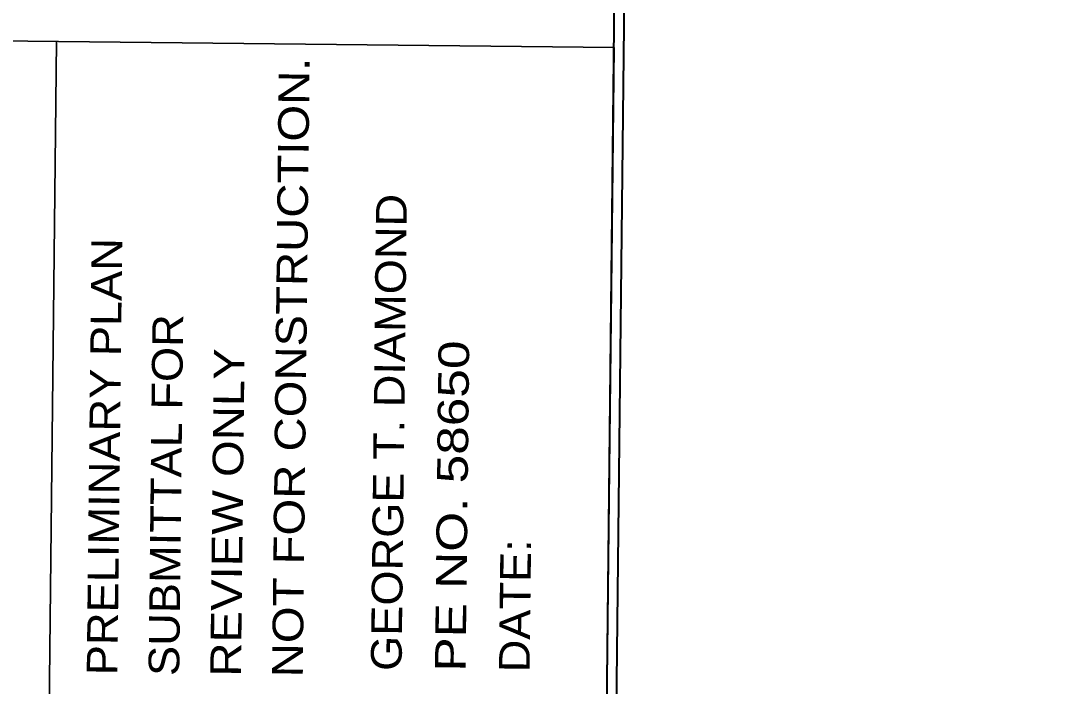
# Model space of a CAD drawing. Extents: x 2356576 to 2377878, y 6966390 to 6990634.
# Drawn here: x 2366630 to 2367164, y 6969128 to 6969467 of the extents above; entities that cross this region are included whole.
import ezdxf

# ---------------------------------------------------------------- set-up
doc = ezdxf.new("R2010")
doc.units = 0
doc.header["$LTSCALE"] = 7.1
doc.layers.add('19', color=7, linetype='Continuous', lineweight=13)
doc.layers.add('8', color=7, linetype='Continuous', lineweight=13)

msp = doc.modelspace()

# ---------------------------------------------------------------- linework, layer by layer
at = {"layer": '19', "lineweight": 35}
for p, q in [((2366931.855, 6969453.45), (2366226.339, 6969461.286)), ((2366647.707, 6969456.606), (2366638.741, 6968649.392)), ((2366931.855, 6969453.45), (2366922.891, 6968646.236))]:
    msp.add_line(p, q, dxfattribs=at)
at = {"layer": '19', "lineweight": 40}
msp.add_lwpolyline([(2363758.773, 6990629.355), (2367158.576, 6990592.767), (2366922.891, 6968646.236), (2363523.088, 6968682.826)], close=True, dxfattribs=at)
at = {"layer": '8', "lineweight": 35}
for p, q in [((2366931.855, 6969453.45), (2366226.339, 6969461.286)), ((2366647.707, 6969456.606), (2366638.741, 6968649.392)), ((2366931.855, 6969453.45), (2366922.891, 6968646.236))]:
    msp.add_line(p, q, dxfattribs=at)
at = {"layer": '8', "lineweight": 40}
for points in [[(2363753.827, 6990634.409), (2367163.63, 6990597.713), (2366927.837, 6968641.182), (2363518.034, 6968677.88)], [(2363758.773, 6990629.355), (2367158.576, 6990592.767), (2366922.891, 6968646.236), (2363523.088, 6968682.826)]]:
    msp.add_lwpolyline(points, close=True, dxfattribs=at)

# ---------------------------------------------------------------- texts
at = {"layer": '19'}
for s, height, width, p in [('NOT FOR CONSTRUCTION.', 15.66, 1.15, (2366773.139, 6969132.546)), ('GEORGE T. DIAMOND', 15.65, 1.1, (2366823.485, 6969135.828)), ('PRELIMINARY PLAN', 15.66, 1.1, (2366678.683, 6969133.594)), ('SUBMITTAL FOR', 15.66, 1.1, (2366710.171, 6969133.246)), ('PE NO. 58650', 15.65, 1.25, (2366856.123, 6969135.466)), ('REVIEW ONLY', 15.66, 1.15, (2366741.651, 6969132.896)), ('DATE: ', 15.65, 1.1, (2366888.763, 6969135.102))]:
    msp.add_text(s, height=height, rotation=89.364, dxfattribs=dict(at, width=width)).set_placement(p)
at = {"layer": '8'}
for s, height, width, p in [('NOT FOR CONSTRUCTION.', 15.66, 1.15, (2366773.139, 6969132.546)), ('GEORGE T. DIAMOND', 15.65, 1.1, (2366823.485, 6969135.828)), ('PRELIMINARY PLAN', 15.66, 1.1, (2366678.683, 6969133.594)), ('SUBMITTAL FOR', 15.66, 1.1, (2366710.171, 6969133.246)), ('PE NO. 58650', 15.65, 1.25, (2366856.123, 6969135.466)), ('REVIEW ONLY', 15.66, 1.15, (2366741.651, 6969132.896)), ('DATE: ', 15.65, 1.1, (2366888.763, 6969135.102))]:
    msp.add_text(s, height=height, rotation=89.364, dxfattribs=dict(at, width=width)).set_placement(p)

doc.saveas('drawing.dxf')
